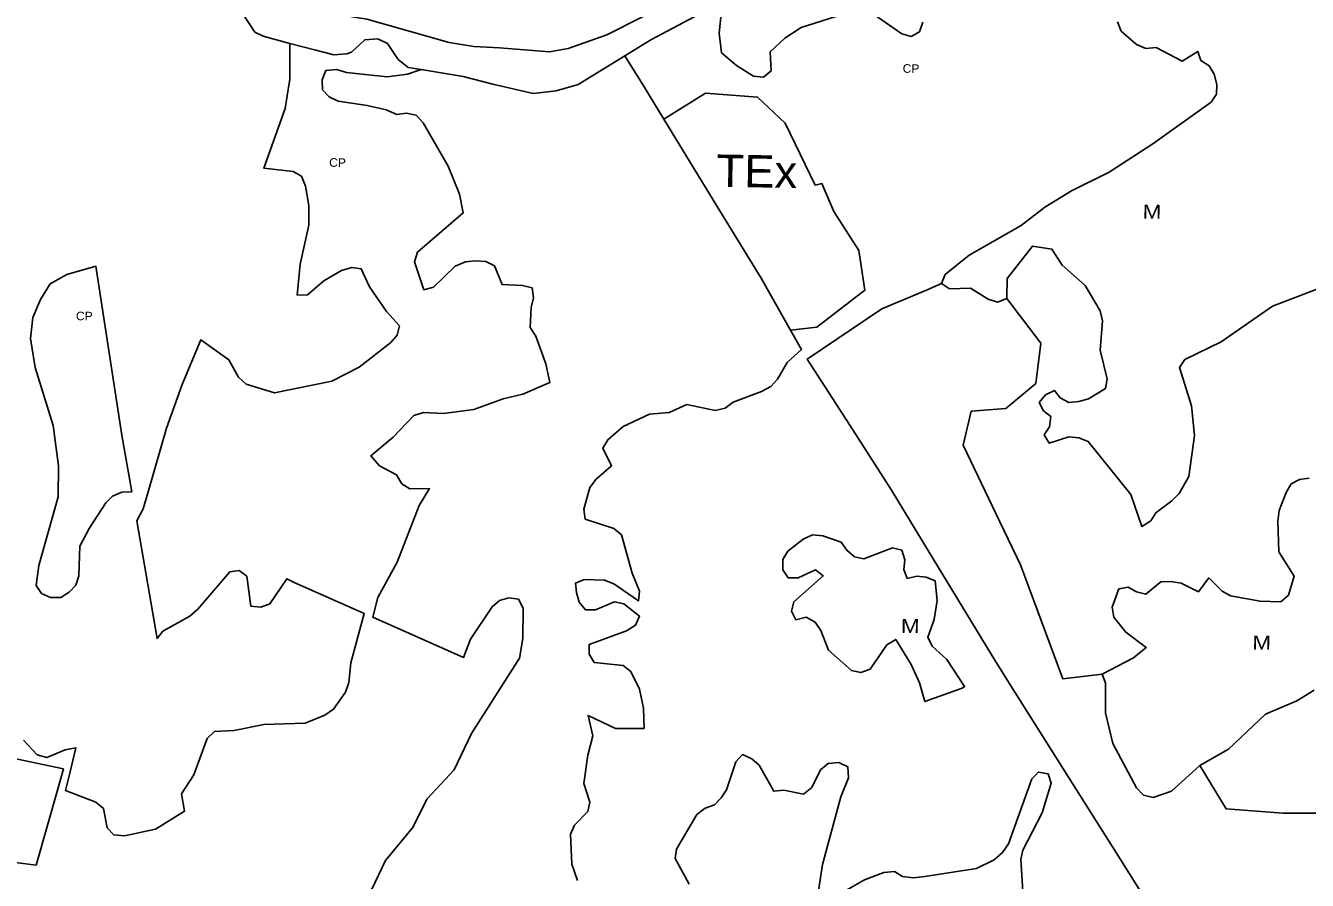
# Model space of a CAD drawing. Extents: x 713589 to 726391, y 7177764 to 7191819.
# Drawn here: x 718159 to 719111, y 7178720 to 7179355 of the extents above; entities that cross this region are included whole.
import ezdxf
from ezdxf.enums import TextEntityAlignment as Align

# ---------------------------------------------------------------- set-up
doc = ezdxf.new("R2010")
doc.units = 0
doc.header["$LTSCALE"] = 2.6
doc.layers.add('63', color=7, linetype='Continuous', lineweight=25)

msp = doc.modelspace()

# ---------------------------------------------------------------- linework, layer by layer
at = {"layer": '63'}
for points in [[(718318.21, 7179372.75), (718319.56, 7179364.12), (718329.01, 7179349.91), (718335.11, 7179346.85), (718355.01, 7179341.55)], [(718630.89, 7179368.45), (718593.31, 7179349.29), (718590.38, 7179347.8), (718561.58, 7179337.81), (718547.69, 7179335.36), (718510.76, 7179338.33), (718491.64, 7179339.27), (718473.39, 7179342.21), (718412.17, 7179359.53), (718377, 7179365.12), (718350.48, 7179374.31)], [(718603.73, 7179332.36), (718622.91, 7179344.13), (718655.66, 7179361.46), (718672.71, 7179370.23)], [(718675.15, 7179363.52), (718673.83, 7179349.04), (718675.48, 7179334.56), (718686.66, 7179325.02), (718699.17, 7179317.12), (718706.73, 7179316.46), (718712.33, 7179321.07), (718711.67, 7179335.22), (718722.54, 7179345.42), (718734.71, 7179353.31), (718770.58, 7179364.82)], [(718785.06, 7179365.48), (718809.41, 7179348.69), (718816.32, 7179346.72), (718822.57, 7179350.01), (718824.88, 7179357.24)], [(718969.55, 7179357.48), (718972.18, 7179350.57)], [(718355.01, 7179341.55), (718374.34, 7179336.41), (718387.71, 7179333.05), (718397.31, 7179333.71), (718400.86, 7179335.08), (718410.71, 7179344.09), (718420.33, 7179344.9), (718427.41, 7179341.4), (718433.87, 7179331.82), (718435.44, 7179329.49), (718442.81, 7179323.61), (718452.46, 7179322.03)], [(718972.18, 7179350.57), (718983.69, 7179340.7), (718990.6, 7179337.73), (718998.17, 7179338.39), (719017.6, 7179328.22), (719029.17, 7179335.61), (719031.41, 7179328.84), (719037.66, 7179324.89), (719041.28, 7179318.64), (719043.25, 7179311.07), (719042.92, 7179303.83), (719038.97, 7179297.91), (718995.86, 7179266.98), (718963.27, 7179245.93), (718935.3, 7179232.11), (718915.55, 7179219.94), (718898.11, 7179206.12), (718859.28, 7179184.08), (718841.5, 7179169.93), (718838.9, 7179163.09), (718838.82, 7179163.06)], [(718249.82, 7179008.43), (718263.48, 7179055.59), (718275.01, 7179088.16), (718288.93, 7179121.38), (718309.78, 7179106.31), (718316.74, 7179093.64), (718322.45, 7179088.25), (718343.67, 7179081.91), (718386.12, 7179090.46), (718406.4, 7179100.91), (718429.84, 7179119.28), (718434.6, 7179124.66), (718436.5, 7179131.63), (718426.68, 7179142.4), (718414.01, 7179160.78), (718407.99, 7179174.09), (718401.02, 7179175.04), (718393.42, 7179172.82), (718380.11, 7179165.22), (718368.07, 7179154.77), (718360.47, 7179154.45), (718362.69, 7179177.58), (718369.03, 7179206.41), (718369.04, 7179220.98), (718366.5, 7179235.55), (718363.66, 7179242.84), (718357.32, 7179246.32), (718335.54, 7179248.9), (718351.39, 7179293.16), (718352.72, 7179301.16), (718355.01, 7179314.88), (718355.01, 7179325.56), (718355.01, 7179341.55)], [(718452.46, 7179322.03), (718483.61, 7179316.92), (718505.75, 7179311.24), (718535.67, 7179304.37), (718552.69, 7179306.35), (718568.98, 7179311.03), (718603.73, 7179332.36)], [(718603.73, 7179332.36), (718618.02, 7179309.14), (718632.59, 7179285.29)], [(718452.46, 7179322.03), (718442.23, 7179318.54), (718427.34, 7179316.64), (718396.93, 7179319.81), (718389.65, 7179322.03), (718381.73, 7179321.4), (718378.87, 7179314.43), (718379.19, 7179307.14), (718384.26, 7179301.76), (718390.91, 7179298.59), (718412.45, 7179295.42), (718426.39, 7179292.25), (718434.31, 7179288.76), (718441.59, 7179289.71), (718448.88, 7179288.12), (718453.95, 7179282.42), (718472.63, 7179250.42), (718480.86, 7179229.51), (718483.71, 7179215.57), (718449.81, 7179186.43), (718447.59, 7179179.15), (718454.56, 7179158.55), (718461.53, 7179160.45), (718477.69, 7179175.97), (718485.29, 7179179.14), (718492.89, 7179180.09), (718500.5, 7179179.45), (718506.83, 7179176.29), (718512.53, 7179162.35), (718527.74, 7179161.71), (718535.02, 7179159.81), (718535.97, 7179152.52), (718534.07, 7179145.24), (718533.43, 7179130.35), (718537.55, 7179124.01), (718545.15, 7179103.42), (718548, 7179089.48), (718528.04, 7179080.93), (718513.47, 7179077.45), (718491.61, 7179069.53), (718469.12, 7179066.68), (718454.23, 7179067.32), (718446.94, 7179065.1), (718431.73, 7179048.95), (718415.21, 7179035.14), (718421.59, 7179027.73), (718434.26, 7179021.07), (718438.06, 7179014.42), (718444.08, 7179010.62), (718458.65, 7179010.93), (718451.05, 7178998.26), (718434.57, 7178956.13), (718420.31, 7178929.84), (718416.53, 7178915.16), (718484, 7178885.33), (718489.04, 7178898.78), (718505.2, 7178922.85), (718510.59, 7178927.61), (718517.56, 7178929.51), (718524.85, 7178928.55), (718528.33, 7178921.9), (718528.01, 7178899.41), (718525.47, 7178884.84), (718489.98, 7178828.77), (718476.99, 7178801.85), (718457.03, 7178780.31), (718445.94, 7178758.77), (718425.97, 7178734.38), (718415.83, 7178713.16)], [(718632.59, 7179285.29), (718663.5, 7179304.55), (718702.33, 7179301.59), (718722.73, 7179282.17), (718745.01, 7179236.26), (718750.05, 7179237.37), (718758.92, 7179216.68), (718777.34, 7179187.71), (718781.94, 7179158.1), (718746.4, 7179130.79), (718726.84, 7179128.41)], [(718726.84, 7179128.41), (718704.82, 7179167.06), (718672.32, 7179220.26), (718632.59, 7179285.29)], [(718887.25, 7179152.09), (718887.57, 7179166.96), (718906.33, 7179190.98), (718920.81, 7179188.68), (718928.38, 7179176.83), (718945.49, 7179161.69), (718956.67, 7179142.93), (718958.32, 7179135.36), (718956.67, 7179113.64), (718961.93, 7179092.25), (718960.61, 7179085.01), (718948.11, 7179077.45), (718940.87, 7179075.47), (718933.3, 7179074.82), (718927.05, 7179078.11), (718922.77, 7179083.7), (718916.19, 7179080.41), (718911.25, 7179074.82), (718914.54, 7179068.57), (718920.13, 7179064.29), (718919.14, 7179056.72), (718915.19, 7179050.8), (718918.81, 7179044.54), (718933.29, 7179049.15), (718940.86, 7179048.49), (718947.77, 7179045.86), (718979.36, 7179006.36), (718987.58, 7178982.67), (718994.16, 7178986.94), (718998.11, 7178992.87), (719009.96, 7179001.75), (719015.22, 7179007.01), (719022.47, 7179019.85), (719026.75, 7179050.12), (719024.45, 7179072.17), (719015.57, 7179100.8), (719019.52, 7179106.72), (719046.51, 7179119.88), (719084.68, 7179146.2), (719119.57, 7179159.68)], [(718838.82, 7179163.06), (718828.12, 7179158.53), (718794.44, 7179144.27), (718739.17, 7179106.93), (718770.73, 7179057.83), (718801.73, 7179009.6), (718825.05, 7178971.22), (718875.74, 7178887.82), (718880.38, 7178880.19), (718880.89, 7178879.35), (718890.45, 7178864.16), (718971.65, 7178735.2), (719013.14, 7178669.3), (719106.43, 7178521.14), (719111.47, 7178513.14), (719136.8, 7178470.37), (719165.62, 7178428.86), (719189.56, 7178386.56), (719224.52, 7178313.68)], [(718838.82, 7179163.06), (718844.79, 7179159.07), (718860.26, 7179159.73), (718873.42, 7179151.5), (718880.33, 7179149.2), (718887.25, 7179152.09)], [(718887.25, 7179152.09), (718912.57, 7179118.92), (718908.95, 7179088.97), (718886.57, 7179070.22), (718883.49, 7179069.98), (718860.9, 7179068.25), (718854.97, 7179042.91), (718882.11, 7178986.08), (718897.41, 7178954.05), (718928.84, 7178869.44), (718958.03, 7178872.86)], [(718726.84, 7179128.41), (718734.93, 7179114.21), (718724.14, 7179104.34), (718717.17, 7179091.98), (718712.1, 7179086.6), (718705.13, 7179082.8), (718684.22, 7179074.88), (718678.2, 7179070.45), (718670.91, 7179068.87), (718649.69, 7179073.3), (718636.7, 7179067.29), (718622.12, 7179066.02), (718602.48, 7179056.84), (718591.08, 7179047.02), (718587.27, 7179040.69), (718593.92, 7179027.7), (718582.52, 7179017.88), (718577.76, 7179011.54), (718573.33, 7178995.39), (718574.28, 7178988.1), (718595.5, 7178981.13), (718601.2, 7178976.38), (718609.12, 7178947.86), (718614.5, 7178934.56), (718613.86, 7178927.27), (718595.49, 7178939.95), (718588.52, 7178942.8), (718573.63, 7178943.12), (718566.98, 7178940.58), (718567.93, 7178933.61), (718569.83, 7178926.33), (718574.58, 7178920.62), (718581.87, 7178920.62), (718596.12, 7178926.64), (718603.09, 7178925.05), (718614.49, 7178915.87), (718611.64, 7178909.21), (718604.99, 7178905.1), (718577.11, 7178894.96), (718577.11, 7178887.68), (718580.91, 7178881.66), (718602.45, 7178879.44), (718608.15, 7178875), (718614.49, 7178861.7), (718617.65, 7178847.76), (718617.97, 7178832.55), (718596.74, 7178832.55), (718576.38, 7178842.23), (718579.95, 7178827.17), (718576.15, 7178812.6), (718573.29, 7178791.69), (718577.72, 7178777.75), (718576.14, 7178770.78), (718566.32, 7178760.65), (718563.46, 7178754), (718564.41, 7178731.82), (718568.66, 7178719.67)], [(719111.97, 7179018.51), (719104.73, 7179017.53), (719098.48, 7179014.24), (719094.86, 7179007.99), (719089.59, 7178994.5), (719088.6, 7178986.6), (719089.26, 7178963.89), (719100.77, 7178945.79), (719096.49, 7178931.64), (719090.9, 7178926.71), (719075.43, 7178927.04), (719053.38, 7178930.99), (719047.13, 7178934.61), (719037.36, 7178944.41), (719029.64, 7178934.08), (719016.86, 7178940.54), (719008.96, 7178941.86), (719001.72, 7178941.53), (718990.53, 7178932.32), (718983.62, 7178933.97), (718977.37, 7178937.59), (718970.46, 7178936.27), (718965.52, 7178922.78), (718966.84, 7178915.21), (718975.72, 7178904.02), (718990.89, 7178892.63), (718981.43, 7178885), (718958.03, 7178872.86)], [(718157.15, 7178823.94), (718167.35, 7178813.08), (718174.59, 7178811.1), (718188.09, 7178816.69), (718196.18, 7178818.08), (718191.7, 7178799.25), (718188.34, 7178786.41), (718210.88, 7178777.82), (718216.58, 7178773.06), (718219.43, 7178758.81), (718224.18, 7178753.42), (718232.1, 7178752.79), (718255.23, 7178757.85), (718276.77, 7178771.05), (718274.59, 7178784.09), (718283.75, 7178798.08), (718293.57, 7178825), (718298.96, 7178830.39), (718313.53, 7178831.02), (718335.71, 7178835.45), (718366.43, 7178836.4), (718381.01, 7178842.41), (718387.34, 7178846.85), (718396.22, 7178859.52), (718398.75, 7178866.8), (718400.34, 7178881.37), (718410.17, 7178917.97), (718358.22, 7178940.94), (718352.66, 7178943.78), (718340.16, 7178925.1), (718333.5, 7178922.57), (718325.9, 7178923.52), (718323.05, 7178945.7), (718317.35, 7178949.81), (718310.38, 7178948.87), (718286.62, 7178921.31), (718280.6, 7178915.92), (718260.64, 7178904.84), (718256.44, 7178899.38), (718241.31, 7178986.74), (718246.13, 7178995.7), (718249.82, 7179008.43)], [(718958.03, 7178872.86), (718960.57, 7178866.18), (718960.57, 7178844.13), (718966.16, 7178821.43), (718983.6, 7178788.52), (718988.86, 7178782.92), (718996.1, 7178781.27), (719009.59, 7178785.88), (719030.63, 7178805)], [(719030.63, 7178805), (719052.05, 7178817.13), (719079.36, 7178843.12), (719102.73, 7178852.99), (719115.57, 7178860.89)], [(718651.52, 7178716.92), (718641.07, 7178735.93), (718642.03, 7178742.89), (718657.24, 7178768.55), (718663.26, 7178773.3), (718670.23, 7178775.84), (718675.29, 7178780.9), (718679.1, 7178786.92), (718686.07, 7178807.83), (718691.14, 7178813.21), (718698.11, 7178810.04), (718703.49, 7178805.29), (718714.26, 7178785.96), (718721.86, 7178786.6), (718736.44, 7178783.74), (718742.46, 7178788.81), (718749.11, 7178801.8), (718754.81, 7178806.55), (718762.73, 7178807.18), (718769.39, 7178804.01), (718769.7, 7178795.78), (718764, 7178781.84), (718750.37, 7178731.47), (718747.19, 7178710.56)], [(718762.72, 7178709.29), (718781.73, 7178720.06), (718795.98, 7178725.44), (718803.9, 7178726.39), (718809.92, 7178722.59), (718818.16, 7178721.64), (718826.39, 7178722.59), (718864.73, 7178728.6), (718878.03, 7178734.93), (718884.05, 7178740.32), (718888.49, 7178746.97), (718905.92, 7178795.12), (718910.99, 7178800.19), (718917.96, 7178798.92), (718920.17, 7178791.95), (718913.52, 7178769.77), (718899.26, 7178742.22), (718897.67, 7178735.25), (718899.25, 7178711.8)], [(719030.63, 7178805), (719050.19, 7178772.78), (719092.19, 7178769.74), (719130.54, 7178769.74)]]:
    msp.add_lwpolyline(points, dxfattribs=at)
for points in [[(718168.69, 7178953.59), (718182.85, 7179004.59), (718183.19, 7179027.63), (718179.24, 7179057.57), (718165.76, 7179100.69), (718162.47, 7179122.4), (718164.12, 7179137.87), (718169.72, 7179151.36), (718176.96, 7179162.88), (718189.46, 7179169.79), (718211, 7179175.91), (718230.29, 7179050.38), (718237.58, 7179008.29), (718230.24, 7179008.21), (718223.33, 7179005.24), (718218.39, 7179000.31), (718205.88, 7178981.23), (718198.97, 7178968.06), (718198.31, 7178946.02), (718196, 7178939.11), (718191.07, 7178933.84), (718184.81, 7178929.89), (718177.25, 7178929.9), (718170.67, 7178932.86), (718166.72, 7178938.78)], [(718743.12, 7178976.35), (718750.72, 7178975.72), (718764.35, 7178970.96), (718768.46, 7178964.94), (718774.16, 7178960.19), (718781.13, 7178958.6), (718802.36, 7178966.84), (718809.33, 7178964.93), (718811.55, 7178957.96), (718810.91, 7178950.68), (718813.44, 7178944.03), (718820.41, 7178945.61), (718827.38, 7178944.97), (718834.03, 7178942.12), (718835.62, 7178927.55), (718833.4, 7178913.61), (718828.64, 7178900.31), (718831.81, 7178893.65), (718842.89, 7178883.83), (718855.95, 7178863.64), (718854.3, 7178862.6), (718826.39, 7178852.55), (718822.62, 7178866.41), (718816.28, 7178880.03), (718804.88, 7178898.73), (718798.23, 7178894.61), (718785.87, 7178876.55), (718778.9, 7178874.02), (718771.93, 7178875.61), (718754.83, 7178890.82), (718749.13, 7178905.39), (718745.01, 7178911.41), (718738.36, 7178915.21), (718730.76, 7178913.31), (718727.59, 7178919.65), (718729.17, 7178926.62), (718751.04, 7178945.94), (718745.33, 7178950.37), (718732.35, 7178944.36), (718725.06, 7178944.36), (718720.94, 7178950.38), (718720.94, 7178957.98), (718724.75, 7178964.32), (718736.15, 7178973.18)], [(718166.7, 7178730.94), (718182.91, 7178788.48), (718186.87, 7178802.54), (718129.01, 7178814.82), (718110.71, 7178738.26)]]:
    msp.add_lwpolyline(points, close=True, dxfattribs=at)

# ---------------------------------------------------------------- texts
for s, height, width, p in [('CP', 6.4, 1.05, (718816.19, 7179319.63)), ('TEx', 24, 1.05, (718701.56, 7179234.54)), ('CP', 6.4, 1.05, (718390.35, 7179249.81)), ('M', 10.4, 1.2, (718995.08, 7179211.27)), ('CP', 6.4, 1.05, (718202.34, 7179135.77)), ('M', 10.4, 1.2, (718815.56, 7178903.48)), ('M', 10.4, 1.2, (719076.52, 7178891.14))]:
    msp.add_text(s, height=height, rotation=359.062, dxfattribs=dict(at, width=width)).set_placement(p, align=Align.CENTER)

doc.saveas('drawing.dxf')
